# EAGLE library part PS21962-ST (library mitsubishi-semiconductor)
600V/5A low-loss 5th generation IGBT inverter bridge for three phase DC-to-AC power conversion Open emitter type Source: Data sheet
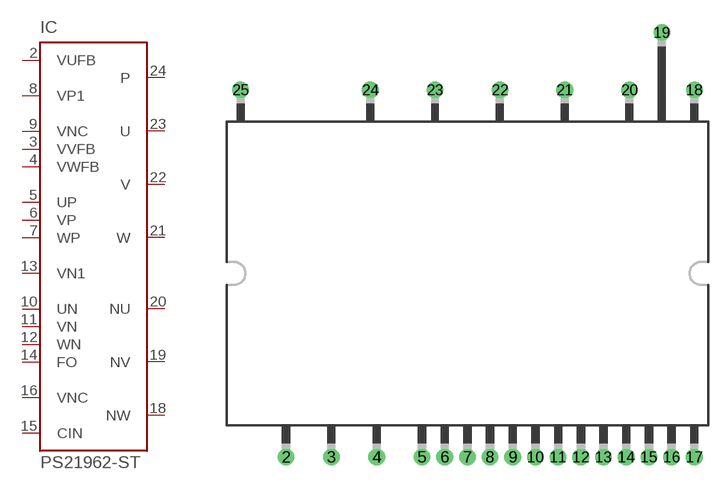
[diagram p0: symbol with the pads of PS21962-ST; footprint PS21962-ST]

Designator prefix IC

## PS21962-ST (OC_FARNELL: unknown; OC_NEWARK: unknown)  [PS21962-ST]
2  VUFB  in
3  VVFB  in
4  VWFB  in
5  UP  in
6  VP  in
7  WP  in
8  VP1  in
9  VNC  in
10  UN  in
11  VN  in
12  WN  in
13  VN1  in
14  FO  in
15  CIN  pas
16  VNC  in
18  NW  out
19  NV  out
20  NU  out
21  W  oc
22  V  oc
23  U  oc
24  P  oc

## Footprint PS21962-ST (pad centres in mm)
DIPIPM 25 Source: Data sheet
drill 0.8 pad 1.27 round: 2 -14.224,-14.4; 3 -10.668,-14.4; 4 -7.112,-14.4; 5 -3.564,-14.4; 6 -1.786,-14.4; 7 -0.008,-14.4; 8 1.77,-14.4; 9 3.548,-14.4; 10 5.326,-14.4; 11 7.104,-14.4; 12 8.882,-14.4; 13 10.66,-14.4; 14 12.438,-14.4; 15 14.216,-14.4; 16 15.994,-14.4; 17 17.772,-14.4; 18 17.78,14.4; 19 15.24,18.9; 20 12.7,14.4; 21 7.62,14.4; 22 2.54,14.4; 23 -2.54,14.4; 24 -7.62,14.4; 25 -17.78,14.4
